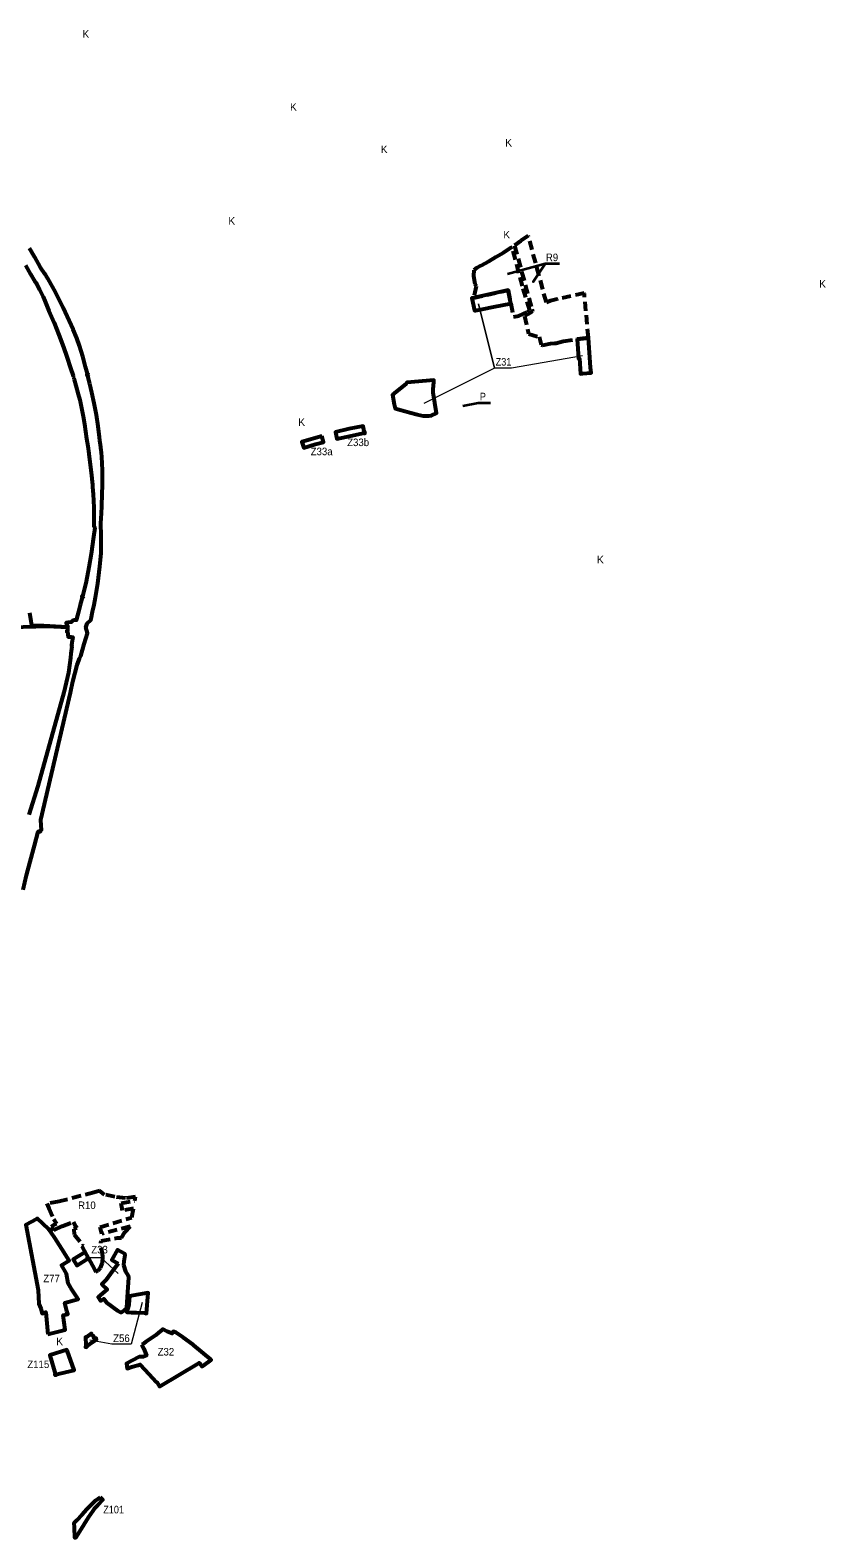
# Model space of a CAD drawing. Extents: x -650246 to -642674, y -1074280 to -1066767.
# Drawn here: x -645200 to -642674, y -1073665 to -1068875 of the extents above; entities that cross this region are included whole.
import ezdxf

# ---------------------------------------------------------------- set-up
doc = ezdxf.new("R2010")
doc.units = 0
doc.header["$LTSCALE"] = 9.6
doc.header["$PDMODE"] = 32
doc.header["$PDSIZE"] = 4.8
doc.linetypes.add('MEDIUM_DASHED', pattern=[4.5, 3, -1.5])
for name, color, linetype, lineweight in [('42', 7, 'Continuous', 25), ('44', 7, 'Continuous', 53), ('45', 7, 'Continuous', 53), ('46', 7, 'Continuous', 13), ('48', 7, 'Continuous', 13), ('60', 7, 'Continuous', 35), ('61', 7, 'MEDIUM_DASHED', 53), ('62', 7, 'Continuous', 35)]:
    doc.layers.add(name, color=color, linetype=linetype, lineweight=lineweight)

msp = doc.modelspace()

# ---------------------------------------------------------------- linework, layer by layer
at = {"layer": '42'}
msp.add_lwpolyline([(-644845.72, -1073050.14), (-644839.57, -1073064.5), (-644830.81, -1073084.98), (-644840.89, -1073089.3), (-644853.8, -1073089.99), (-644856.4, -1073090.13), (-644894.15, -1073110.3), (-644892.14, -1073126.36), (-644877.32, -1073121.83), (-644856.97, -1073115.6), (-644851, -1073113.77), (-644822.62, -1073144.71), (-644811.96, -1073156.75), (-644799.26, -1073170.13), (-644798.38, -1073169.56), (-644792.59, -1073178.73), (-644789.31, -1073183.93), (-644663.17, -1073108.27), (-644656.56, -1073117.4), (-644654.61, -1073120.1), (-644649.7, -1073116.65), (-644625.26, -1073099.51), (-644680.69, -1073053.67), (-644684.09, -1073050.8), (-644714.42, -1073027.62), (-644714.42, -1073027.62), (-644737.88, -1073012.62), (-644745.73, -1073008.64), (-644748.95, -1073015.64), (-644757.73, -1073012.05), (-644764.69, -1073008.87), (-644778.38, -1073001.84), (-644781.52, -1073004.39), (-644793.743, -1073014.293), (-644801.54, -1073020.61), (-644824.08, -1073036.56), (-644832.7, -1073042.34), (-644839.47, -1073046.89)], close=True, dxfattribs=at)
at = {"layer": '44'}
for points in [[(-645017.46, -1069970.61), (-645018.28, -1069967.49), (-645024.45, -1069944.43), (-645032.85, -1069912.07), (-645043.5, -1069878.37), (-645051.78, -1069854.2), (-645063.26, -1069825.99), (-645095.1, -1069757.62), (-645118.98, -1069710.08), (-645143.56, -1069664.05), (-645148.8, -1069656.1), (-645150.3, -1069653.84), (-645153.33, -1069649.24), (-645166.67, -1069629), (-645184.88, -1069596.58), (-645202.56, -1069568.23)], [(-645214.76, -1069622.37), (-645198.41, -1069650.49), (-645185.17, -1069673.38), (-645179.12, -1069681.3), (-645170.3, -1069698.91), (-645158.43, -1069722.61), (-645153.44, -1069734.71), (-645140.27, -1069766.68), (-645123.84, -1069805.38), (-645108.74, -1069843.58), (-645094.42, -1069882.65), (-645083.31, -1069913.37), (-645071.53, -1069948.89), (-645063.96, -1069973.73), (-645063.23, -1069976.2), (-645062.57, -1069978.46), (-645061.76, -1069981.21), (-645060.612, -1069985.022), (-645054.73, -1070004.56), (-645047.28, -1070031.83), (-645042.27, -1070049.23), (-645032.21, -1070102.73), (-645027.49, -1070126.56), (-645021.14, -1070173.07), (-645018.56, -1070184.92), (-645016.92, -1070196.32), (-645013.77, -1070220.04), (-645013.51, -1070222.04), (-645005.98, -1070280.14), (-645002.308, -1070319.268), (-645001.81, -1070324.58), (-645001.64, -1070326.4)], [(-645166.34, -1071384.07), (-645071.99, -1070980.72), (-645064.39, -1070944.7), (-645050.47, -1070891.48), (-645045.74, -1070877.19), (-645043, -1070871.35), (-645039.25, -1070863.33), (-645028.25, -1070824.83), (-645018.18, -1070791.34), (-645023.25, -1070772.62), (-645019.57, -1070760.07), (-645007.68, -1070749.5), (-645006.739, -1070745.384), (-645001.71, -1070723.39), (-644997.14, -1070700.88), (-644992.6, -1070677.92), (-644985.04, -1070633.43), (-644978.44, -1070578.56), (-644975.05, -1070536.16), (-644974.44, -1070482.48), (-644975.29, -1070440.14), (-644974.69, -1070427.86), (-644972.48, -1070389.15), (-644971.37, -1070345.98), (-644970.61, -1070323.44), (-644970.55, -1070321.56), (-644970.524, -1070315.358), (-644970.36, -1070275.49), (-644971.47, -1070250.14), (-644974, -1070216.2), (-644974.29, -1070213.17), (-644974.49, -1070210.98), (-644976.94, -1070191.41), (-644978.49, -1070180.05), (-644979.57, -1070167.9), (-644984.21, -1070132.81), (-644989.62, -1070097.79), (-644996.88, -1070059.73), (-645004.02, -1070026.44), (-645010.54, -1069999.3)], [(-645010.54, -1069999.3), (-645015.548, -1069978.177), (-645016.01, -1069976.23), (-645016.89, -1069972.82), (-645017.46, -1069970.61)], [(-645001.64, -1070326.4), (-644999.47, -1070349.63), (-644997.87, -1070391.16), (-644998.25, -1070430.5), (-644998.17, -1070450.59), (-644995.14, -1070455.72), (-644998.92, -1070484.58), (-645006.44, -1070538.78), (-645014.07, -1070580.72), (-645022.64, -1070626.93), (-645033.53, -1070674.55)], [(-645033.53, -1070674.55), (-645041, -1070700.44), (-645046.63, -1070722.77), (-645052.4, -1070746.427), (-645053.21, -1070749.75), (-645060.46, -1070749.1), (-645065.17, -1070751.39), (-645070.3, -1070755.92), (-645079.38, -1070756.91), (-645085.58, -1070758.04), (-645081.6, -1070770.362)], [(-645202.41, -1070726.571), (-645197.539, -1070753.128), (-645195.527, -1070765.319), (-645156.988, -1070766.884), (-645100.32, -1070769.5), (-645081.6, -1070770.362), (-645081.75, -1070772.79), (-645125.217, -1070770.81), (-645143, -1070770), (-645161, -1070770), (-645182, -1070771), (-645303, -1070774)], [(-645081.6, -1070770.362), (-645081.75, -1070772.79), (-645081.85, -1070781.59), (-645081.57, -1070783.53), (-645083.95, -1070783.89), (-645083.49, -1070786.92), (-645081.13, -1070786.56), (-645078.85, -1070802.46), (-645070.2, -1070802.33), (-645065.01, -1070803.22), (-645068.07, -1070820.37)], [(-645068.07, -1070820.37), (-645068.52, -1070830.52), (-645068.07, -1070832.72), (-645071.18, -1070855.63), (-645071.77, -1070868.73), (-645078.23, -1070915.65)], [(-645078.23, -1070915.65), (-645092.67, -1070979.52), (-645176.14, -1071277.26), (-645204.341, -1071368.19)], [(-645222.48, -1071606.08), (-645211.27, -1071560.01), (-645199.61, -1071515.68), (-645186.67, -1071465.55), (-645175.06, -1071420.93), (-645167.58, -1071421.19), (-645167.37, -1071415.2), (-645163.56, -1071415.3), (-645164.76, -1071401.79), (-645166.34, -1071384.07)]]:
    msp.add_lwpolyline(points, dxfattribs=at)
msp.add_lwpolyline([(-644977.924, -1073535.072), (-644969.117, -1073544.254), (-644985.66, -1073560.69), (-644996.41, -1073571.97), (-645001.267, -1073578.582), (-645015.55, -1073599.96), (-645043.35, -1073644.04), (-645056.06, -1073664.2), (-645057.87, -1073664.55), (-645059.35, -1073631.3), (-645060.009, -1073616.53), (-645051.513, -1073608.124), (-645035.303, -1073590.199), (-645020.11, -1073573.585), (-644993.044, -1073546.324)], close=True, dxfattribs=at)
for p in [(-645017.46, -1069970.61), (-645033.53, -1070674.55), (-645081.6, -1070770.362)]:
    msp.add_point(p, dxfattribs=at)
at = {"layer": '45'}
for p, q in [((-644138.78, -1070154.07), (-644143.31, -1070132.95)), ((-644182.31, -1070163.66), (-644138.78, -1070154.07))]:
    msp.add_line(p, q, dxfattribs=at)
for points in [[(-643791.88, -1069725.25), (-643797.75, -1069726.51), (-643789.3, -1069766.05), (-643786.35, -1069765.46), (-643764.94, -1069761.27), (-643729.34, -1069754.3), (-643674.3, -1069743.53), (-643682.61, -1069701.16)], [(-643791.88, -1069725.25), (-643797.75, -1069726.51), (-643789.3, -1069766.05), (-643786.35, -1069765.46), (-643764.94, -1069761.27), (-643729.34, -1069754.3), (-643674.3, -1069743.53), (-643682.61, -1069701.16)], [(-643463.51, -1069857.44), (-643459.13, -1069918.47), (-643456.14, -1069918.26), (-643452.63, -1069967.09), (-643446.63, -1069966), (-643419.62, -1069963.66), (-643420.79, -1069947.35), (-643427.6, -1069852.59)], [(-643920.84, -1070026.46), (-643920.29, -1070017.73), (-643920.16, -1070015.69), (-643918.69, -1069992.23), (-643918.88, -1069986.82), (-644004.06, -1069994.59), (-644005.92, -1069998.62), (-644044.7, -1070029.04), (-644050.12, -1070033.64), (-644044.18, -1070064.43), (-644041.71, -1070077.29), (-644022.77, -1070082.66), (-643991.99, -1070091.37), (-643971.03, -1070095.79), (-643951.99, -1070100.35), (-643933.96, -1070100.18), (-643926.33, -1070099.5), (-643909.87, -1070091.95)], [(-643920.84, -1070026.46), (-643920.29, -1070017.73), (-643920.16, -1070015.69), (-643918.69, -1069992.23), (-643918.88, -1069986.82), (-644004.06, -1069994.59), (-644005.92, -1069998.62), (-644044.7, -1070029.04), (-644050.12, -1070033.64), (-644044.18, -1070064.43), (-644041.71, -1070077.29), (-644022.77, -1070082.66), (-643991.99, -1070091.37), (-643971.03, -1070095.79), (-643951.99, -1070100.35), (-643933.96, -1070100.18), (-643926.33, -1070099.5), (-643909.87, -1070091.95)], [(-644274.246, -1070164.59), (-644337.256, -1070182.64), (-644331.096, -1070202.4), (-644294.206, -1070190.9), (-644269.036, -1070184.57)], [(-644274.246, -1070164.59), (-644337.256, -1070182.64), (-644331.096, -1070202.4), (-644294.206, -1070190.9), (-644269.036, -1070184.57)], [(-645144.37, -1073017.64), (-645088.62, -1073003.45), (-645095.04, -1072957.07), (-645080.61, -1072954.43), (-645083.13, -1072944.94), (-645090.34, -1072917.86), (-645047.42, -1072906.05), (-645050.6, -1072901.03), (-645069.55, -1072872.12), (-645071.87, -1072868.45), (-645079.81, -1072855.89), (-645084.47, -1072825.67), (-645100.27, -1072798.46), (-645076.66, -1072783.06), (-645099.58, -1072746.945), (-645121.96, -1072711.68), (-645133.26, -1072694.17), (-645142.1, -1072682.57), (-645176.757, -1072649.968), (-645180.05, -1072651.77), (-645213.34, -1072669.98), (-645174.13, -1072877.93), (-645172.28, -1072921.42), (-645166.48, -1072936.5), (-645162.379, -1072951.55), (-645149.84, -1072948.13)], [(-645025.61, -1072757.17), (-645063.6, -1072780.26), (-645051.94, -1072799.21), (-645015.02, -1072776.01)], [(-645025.61, -1072757.17), (-645063.6, -1072780.26), (-645051.94, -1072799.21), (-645015.02, -1072776.01)], [(-644884.94, -1072897.19), (-644886.98, -1072923.48), (-644889.65, -1072936.67), (-644893.37, -1072942.61), (-644893.59, -1072947.97), (-644878.86, -1072948.42), (-644861.93, -1072948.94), (-644835.99, -1072949.74), (-644830.25, -1072951.9), (-644825.25, -1072885.96)], [(-644884.94, -1072897.19), (-644886.98, -1072923.48), (-644889.65, -1072936.67), (-644893.37, -1072942.61), (-644893.59, -1072947.97), (-644878.86, -1072948.42), (-644861.93, -1072948.94), (-644835.99, -1072949.74), (-644830.25, -1072951.9), (-644825.25, -1072885.96)], [(-645004.82, -1073024.63), (-645005.31, -1073015.68), (-645021.1, -1073026.69), (-645024.71, -1073026.95), (-645023.6, -1073052.12), (-645023.88, -1073058.37), (-645019.57, -1073056.46), (-645007.99, -1073047.31), (-645003.78, -1073043.96), (-644989.34, -1073034.58), (-644990.25, -1073030.54), (-644997.09, -1073032.21), (-644999.23, -1073023.29)], [(-645004.82, -1073024.63), (-645005.31, -1073015.68), (-645021.1, -1073026.69), (-645024.71, -1073026.95), (-645023.6, -1073052.12), (-645023.88, -1073058.37), (-645019.57, -1073056.46), (-645007.99, -1073047.31), (-645003.78, -1073043.96), (-644989.34, -1073034.58), (-644990.25, -1073030.54), (-644997.09, -1073032.21), (-644999.23, -1073023.29)], [(-644845.72, -1073050.14), (-644839.57, -1073064.5), (-644830.81, -1073084.98), (-644840.89, -1073089.3), (-644853.8, -1073089.99), (-644856.4, -1073090.13), (-644894.15, -1073110.3), (-644892.14, -1073126.36), (-644877.32, -1073121.83), (-644856.97, -1073115.6), (-644851, -1073113.77), (-644822.62, -1073144.71), (-644811.96, -1073156.75), (-644799.26, -1073170.13), (-644798.38, -1073169.56), (-644792.59, -1073178.73), (-644789.31, -1073183.93), (-644663.17, -1073108.27), (-644656.56, -1073117.4), (-644654.61, -1073120.1), (-644649.7, -1073116.65), (-644625.26, -1073099.51), (-644680.69, -1073053.67), (-644684.09, -1073050.8), (-644714.42, -1073027.62), (-644714.42, -1073027.62), (-644737.88, -1073012.62), (-644745.73, -1073008.64), (-644748.95, -1073015.64), (-644757.73, -1073012.05), (-644764.69, -1073008.87), (-644778.38, -1073001.84), (-644781.52, -1073004.39), (-644793.743, -1073014.293), (-644801.54, -1073020.61), (-644824.08, -1073036.56), (-644832.7, -1073042.34), (-644839.47, -1073046.89)], [(-644845.72, -1073050.14), (-644839.57, -1073064.5), (-644830.81, -1073084.98), (-644840.89, -1073089.3), (-644853.8, -1073089.99), (-644856.4, -1073090.13), (-644894.15, -1073110.3), (-644892.14, -1073126.36), (-644877.32, -1073121.83), (-644856.97, -1073115.6), (-644851, -1073113.77), (-644822.62, -1073144.71), (-644811.96, -1073156.75), (-644799.26, -1073170.13), (-644798.38, -1073169.56), (-644792.59, -1073178.73), (-644789.31, -1073183.93), (-644663.17, -1073108.27), (-644656.56, -1073117.4), (-644654.61, -1073120.1), (-644649.7, -1073116.65), (-644625.26, -1073099.51), (-644680.69, -1073053.67), (-644684.09, -1073050.8), (-644714.42, -1073027.62), (-644714.42, -1073027.62), (-644737.88, -1073012.62), (-644745.73, -1073008.64), (-644748.95, -1073015.64), (-644757.73, -1073012.05), (-644764.69, -1073008.87), (-644778.38, -1073001.84), (-644781.52, -1073004.39), (-644793.743, -1073014.293), (-644801.54, -1073020.61), (-644824.08, -1073036.56), (-644832.7, -1073042.34), (-644839.47, -1073046.89)], [(-645119.34, -1073145.61), (-645060.1, -1073131.68), (-645082.6, -1073069.93), (-645083.681, -1073066.962), (-645137.5, -1073083.97)]]:
    msp.add_lwpolyline(points, close=True, dxfattribs=at)
for points in [[(-644143.31, -1070132.95), (-644143.31, -1070132.95), (-644143.31, -1070132.95), (-644187.11, -1070141.58), (-644230.4, -1070152.08), (-644226.23, -1070173.28), (-644182.31, -1070163.66)], [(-644143.31, -1070132.95), (-644143.31, -1070132.95), (-644143.31, -1070132.95), (-644187.11, -1070141.58), (-644230.4, -1070152.08), (-644226.23, -1070173.28), (-644182.31, -1070163.66)], [(-644182.31, -1070163.66), (-644138.78, -1070154.07), (-644143.31, -1070132.95)], [(-644902.18, -1072797.88), (-644901.35, -1072785.36), (-644898.29, -1072766.55), (-644899.2, -1072762.14), (-644922.88, -1072749.97), (-644940.8, -1072781.48), (-644920.46, -1072792.92)], [(-644902.18, -1072797.88), (-644901.35, -1072785.36), (-644898.29, -1072766.55), (-644899.2, -1072762.14), (-644922.88, -1072749.97), (-644940.8, -1072781.48), (-644920.46, -1072792.92)], [(-644920.46, -1072792.92), (-644945.2, -1072826.3), (-644959.24, -1072844.92), (-644972.28, -1072859.02), (-644969.93, -1072861.43), (-644955.49, -1072875.78), (-644983.93, -1072900.24), (-644977.16, -1072912.11), (-644966.57, -1072905.23), (-644957.79, -1072916.73), (-644921.18, -1072943.17), (-644911.87, -1072948.76), (-644900.2, -1072941.67), (-644893.77, -1072935.88), (-644892.86, -1072932.6), (-644891.2, -1072900.09), (-644886.61, -1072837.61), (-644887.99, -1072831.83), (-644896.45, -1072818.78), (-644902.18, -1072797.88)], [(-644920.46, -1072792.92), (-644945.2, -1072826.3), (-644959.24, -1072844.92), (-644972.28, -1072859.02), (-644969.93, -1072861.43), (-644955.49, -1072875.78), (-644983.93, -1072900.24), (-644977.16, -1072912.11), (-644966.57, -1072905.23), (-644957.79, -1072916.73), (-644921.18, -1072943.17), (-644911.87, -1072948.76), (-644900.2, -1072941.67), (-644893.77, -1072935.88), (-644892.86, -1072932.6), (-644891.2, -1072900.09), (-644886.61, -1072837.61), (-644887.99, -1072831.83), (-644896.45, -1072818.78), (-644902.18, -1072797.88)]]:
    msp.add_lwpolyline(points, dxfattribs=at)
for p in [(-644138.78, -1070154.07), (-645119.34, -1073145.61)]:
    msp.add_point(p, dxfattribs=at)
at = {"layer": '46'}
for points in [[(-643446.307, -1069909.57), (-643672.005, -1069949.473), (-643725.65, -1069949.473), (-643725.65, -1069949.473), (-643777.096, -1069744.435), (-643725.65, -1069949.473), (-643950.635, -1070061)], [(-645024.402, -1072773.758), (-644975.968, -1072773.758), (-644921.076, -1072825.098)], [(-644844.691, -1072916.725), (-644879.683, -1073049.795), (-644940.921, -1073049.795), (-645010.906, -1073036.663)], [(-644844.691, -1072916.725), (-644879.683, -1073049.795), (-644940.921, -1073049.795), (-645010.906, -1073036.663)]]:
    msp.add_lwpolyline(points, dxfattribs=at)
at = {"layer": '60'}
msp.add_lwpolyline([(-643738.691, -1070059.84), (-643778.124, -1070059.84), (-643826.476, -1070069.235)], dxfattribs=at)
msp.add_lwpolyline([(-643738.691, -1070059.84), (-643778.124, -1070059.84), (-643826.476, -1070069.235)], dxfattribs=at)
at = {"layer": '61'}
for points in [[(-643743.81, -1069610.19), (-643770.29, -1069624.14), (-643781.95, -1069630.63), (-643791.77, -1069637.88), (-643793.09, -1069656.07), (-643788.14, -1069682.71), (-643784.59, -1069688.47), (-643791.88, -1069725.25), (-643682.61, -1069701.16), (-643674.3, -1069743.53), (-643665.92, -1069785.96), (-643649.25, -1069782.43), (-643621.71, -1069770.11), (-643613.9, -1069765.6), (-643637.36, -1069688.73), (-643669.73, -1069564.16), (-643673.82, -1069567.04), (-643697, -1069582.64), (-643721.43, -1069596.72)], [(-643561.41, -1069740.406), (-643618.737, -1069528.647), (-643643.16, -1069545.42), (-643662.335, -1069558.944), (-643607.44, -1069761.72), (-643605.24, -1069768.92), (-643612.22, -1069772.9), (-643630.77, -1069783.44), (-643618, -1069840.01), (-643584.63, -1069849.66), (-643578.28, -1069874.97), (-643574.05, -1069875.85), (-643567.91, -1069874.7), (-643548.67, -1069871.08), (-643535.83, -1069869.23), (-643530.01, -1069869.17), (-643507.1, -1069863.33), (-643463.51, -1069857.44), (-643427.6, -1069852.59), (-643440.77, -1069713.85), (-643441.08, -1069710.59), (-643527.49, -1069729.78), (-643547.9, -1069735.62)], [(-645107.58, -1072596.47), (-645147.13, -1072602.79), (-645140.96, -1072617.82), (-645125.58, -1072652.42), (-645116.1, -1072667.08), (-645121.26, -1072669.32), (-645133.59, -1072676.49), (-645124.933, -1072686.721), (-645098.016, -1072674.425), (-645062.131, -1072660.856), (-645056.08, -1072674.07), (-645051.87, -1072680.22), (-645061.13, -1072683.98), (-645060.48, -1072700.69), (-645032.11, -1072737.28), (-645036.08, -1072737.88), (-645002.34, -1072799.06), (-644991.3, -1072819.12), (-644984.02, -1072814.87), (-644977, -1072807.06), (-644970.87, -1072790.69), (-644969.63, -1072771.21), (-644975.852, -1072727.059), (-644974.61, -1072720.9), (-644924.08, -1072711.8), (-644909.76, -1072711.64), (-644899.86, -1072693.27), (-644882.85, -1072675.56), (-644972.68, -1072698.65), (-644977.57, -1072677.66), (-644877.32, -1072647.4), (-644871.55, -1072618.07), (-644906.56, -1072624.79), (-644911.21, -1072601.67), (-644867.36, -1072593.58), (-644865.31, -1072581.58), (-644897.87, -1072585.78), (-644931.48, -1072581.26), (-644963.97, -1072574.57), (-644979.55, -1072562.44), (-644997.92, -1072567.23)]]:
    msp.add_lwpolyline(points, close=True, dxfattribs=at)
at = {"layer": '62'}
msp.add_lwpolyline([(-643519.721, -1069617.808), (-643564.914, -1069617.808), (-643602.876, -1069674.79), (-643564.914, -1069617.808), (-643685.127, -1069650.369)], dxfattribs=at)
at = {"layer": '62', "lineweight": 13}
msp.add_lwpolyline([(-643519.721, -1069617.808), (-643564.914, -1069617.808), (-643602.876, -1069674.79), (-643564.914, -1069617.808), (-643685.127, -1069650.369)], dxfattribs=at)

# ---------------------------------------------------------------- texts
at = {"layer": '44', "width": 0.9}
msp.add_text('Z101', height=24, dxfattribs=at).set_placement((-644967.996, -1073586.746))
msp.add_text('Z101', height=24, dxfattribs=at).set_placement((-644967.996, -1073586.746))
at = {"layer": '46'}
for s, width, p in [('Z31', 0.9, (-643722.294, -1069940.847)), ('Z31', 0.9, (-643722.294, -1069940.847)), ('Z33b', 0.95, (-644193.607, -1070196.61)), ('Z33b', 0.95, (-644193.607, -1070196.61)), ('Z33a', 0.95, (-644309.424, -1070225.565)), ('Z33a', 0.95, (-644309.424, -1070225.565)), ('Z33', 0.95, (-645005.989, -1072761.006)), ('Z77', 0.95, (-645158.28, -1072852.64)), ('Z56', 0.95, (-644936.499, -1073042.592)), ('Z56', 0.95, (-644936.499, -1073042.592)), ('Z32', 0.95, (-644795.309, -1073085.354)), ('Z32', 0.95, (-644795.309, -1073085.354)), ('Z115', 0.95, (-645208.897, -1073125.218))]:
    msp.add_text(s, height=24, dxfattribs=dict(at, width=width)).set_placement(p)
at = {"layer": '48'}
for p in [(-645034.002, -1068899.33), (-644374.971, -1069131.317), (-643691.928, -1069244.995), (-644086.887, -1069265.894), (-644570.824, -1069493.226), (-644570.824, -1069493.226), (-643697.851, -1069536.996), (-642695.251, -1069693.065), (-644348.839, -1070132.426), (-643400.597, -1070568.968), (-643400.597, -1070568.968), (-645117.21, -1073052.527)]:
    msp.add_text('K', height=24, dxfattribs=at).set_placement(p)
at = {"layer": '60', "width": 0.9}
msp.add_text('P', height=24, dxfattribs=at).set_placement((-643772.431, -1070051.2))
msp.add_text('P', height=24, dxfattribs=at).set_placement((-643772.431, -1070051.2))
at = {"layer": '62', "width": 0.95}
for s, p in [('R9', (-643562.88, -1069609.148)), ('R9', (-643562.88, -1069609.148)), ('R10', (-645047.84, -1072620.116)), ('R10', (-645047.84, -1072620.116))]:
    msp.add_text(s, height=24, dxfattribs=at).set_placement(p)

doc.saveas('drawing.dxf')
